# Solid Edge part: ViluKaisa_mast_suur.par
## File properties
Author: kaisa
Template: Iso Metric Part.par
Last saved by: kaisa
Revision: 8
Application: Solid Edge
Density: 600.000 kg/m^3
Accuracy: 0.990
Username: kaisa
Material: Wood, Mahogany
Face Style: Tan
Fill Style: Wood (Radial)
Virtual Style: Wood (Radial)
Grouping: Non-metals\Woods
LibraryName: Materials
Coef. of Thermal Exp: 0.0
Thermal Conductivity: 0.0
Specific Heat: 0.0
Modulus of Elasticity: 0.0
Poisson's Ratio: 0.428
Yield Stress: 0.0
Ultimate Stress: 0.0
Elongation: 0.0
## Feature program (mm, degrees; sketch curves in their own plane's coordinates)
sketch for "unnamed RevolvedProtrusion 1" plane through (0, 0, 0) normal (1, 0, 0) x-axis (0, 1, 0)
  line (3, 250) -> (3, 0)
  line (3, 0) -> (0, 0)
  line (0, 0) -> (0, 250)
  line (0, 250) -> (3, 250)
revolve "unnamed RevolvedProtrusion 1" add finite 360 deg
sketch for "unnamed RevolvedProtrusion 2" plane through (-5, 0, 0) normal (1, 0, 0) x-axis (0, 1, 0)
  line (-100, 164.5646) -> (100, 164.5646)
  line (100, 162.8979) -> (100, 164.5646)
  line (-100, 162.8979) -> (100, 162.8979)
  line (-100, 164.5646) -> (-100, 162.8979)
revolve "unnamed RevolvedProtrusion 2" add finite 360 deg
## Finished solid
Body 1: solid body, 6 faces, 4 edges, 0 vertices, 2 separate solids.
  Faces by surface: plane 4, cylinder 2
  Edges by curve: circle 4
Bounding box of the edges (mm): 9.667 x 200.000 x 250.000, from (-6.6667, -100, 0) to (3, 100, 250).
Cylindrical faces by radius (mm): R1.6667 x1, R3 x1
Planar faces by outward normal: +y 1, +z 1, -y 1, -z 1
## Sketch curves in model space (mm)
line (-5, 100, 162.8979) -> (-5, 100, 164.5646)
line (-5, -100, 162.8979) -> (-5, 100, 162.8979)
line (-5, -100, 164.5646) -> (-5, -100, 162.8979)
line (-5, -100, 164.5646) -> (-5, 100, 164.5646)
line (0, 3, 233.7008) -> (0, 0, 233.7008)
line (0, 0, 250) -> (0, 3, 250)
line (0, 3, 250) -> (0, 3, 0)
line (0, 3, 0) -> (0, 0, 0)
line (0, 0, 0) -> (0, 0, 250)
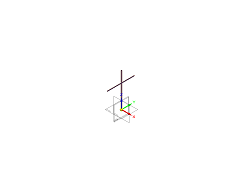
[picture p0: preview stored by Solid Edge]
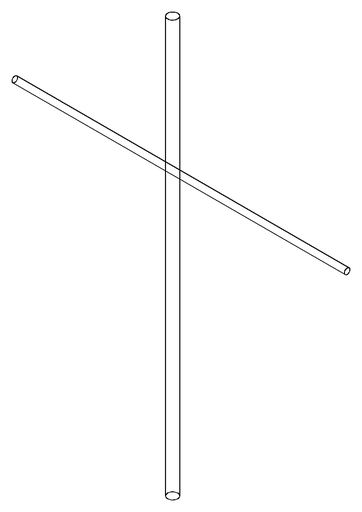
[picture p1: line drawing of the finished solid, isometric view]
